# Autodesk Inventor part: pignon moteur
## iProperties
Shininess: 64.0
Length Units: 11269
Angle Units: 11279
Time Units: 11290
Mass Units: 11283
Length Display Precision: 3
Angle Display Precision: 2
Compacted: True
Part Number: pignon moteur
Document SubType Name: Modeling
Created: 2004-09
Material: Par défaut
Designer: Laurent
Density: 1 g/cm^3
Density: 0.0
Volumn: 0.0
Area: 0.0
PropertySet Name: Model Information
Control State: 0
Master: False
Checked Out: False
Author: Laurent
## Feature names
1. Extrusion1
2. Extrusion2
3. Corps dérivé2 [Tagging]
